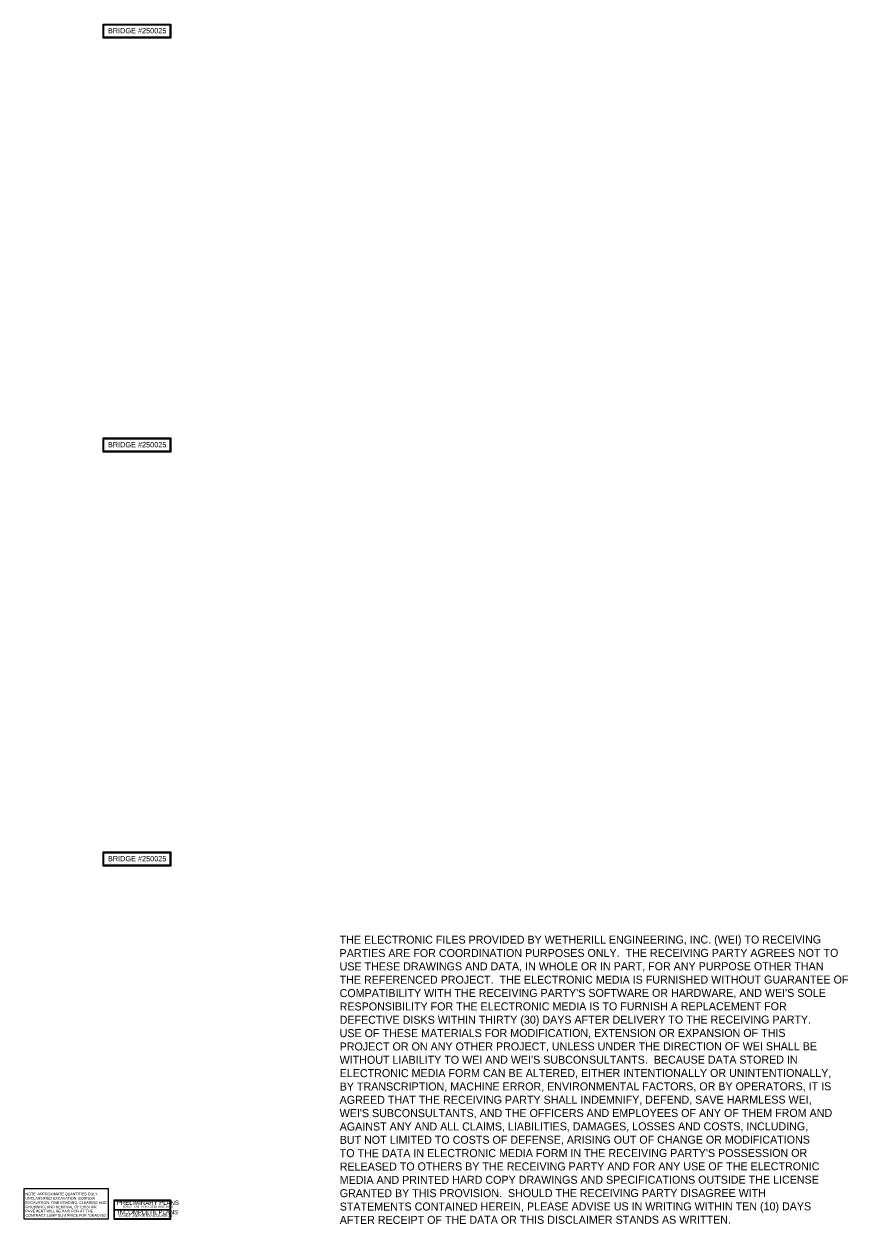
# Model space of a CAD drawing. Extents: x -8 to 533, y -20 to 768.
# Drawn here: x 313.8 to 532.8, y 1.2 to 320 of the extents above; entities that cross this region are included whole.
import ezdxf

# ---------------------------------------------------------------- set-up
doc = ezdxf.new("R2010")
doc.units = 0
for name, color, linetype in [('Default', 7, 'Continuous'), ('Old_Level_1', 7, 'Continuous'), ('Old_Level_34', 7, 'Continuous'), ('Prop Dimension', 7, 'Continuous'), ('Prop Grid Mask', 7, 'Continuous'), ('Sheet Sticker Incomplete CELL', 7, 'Continuous'), ('Sheet Sticker Preliminary CELL', 7, 'Continuous')]:
    doc.layers.add(name, color=color, linetype=linetype)

msp = doc.modelspace()

# ---------------------------------------------------------------- linework, layer by layer
at = {"layer": 'Old_Level_34'}
for points in [[(335.02, 319.75), (352.49, 319.75), (352.49, 316.46), (335.02, 316.46)], [(335.02, 209.75), (352.49, 209.75), (352.49, 206.46), (335.02, 206.46)], [(335.02, 99.75), (352.49, 99.75), (352.49, 96.46), (335.02, 96.46)]]:
    msp.add_lwpolyline(points, close=True, dxfattribs=at)
at = {"layer": 'Prop Grid Mask'}
for points in [[(334.83, 320), (352.75, 320), (352.75, 316.24), (334.83, 316.24)], [(334.83, 210), (352.75, 210), (352.75, 206.24), (334.83, 206.24)], [(334.83, 100), (352.75, 100), (352.75, 96.24), (334.83, 96.24)], [(313.75, 2.5), (336.25, 2.5), (336.25, 10.5), (313.75, 10.5)], [(352.75, 7.5), (337.6, 7.5), (337.6, 2.42), (352.75, 2.42)]]:
    msp.add_lwpolyline(points, close=True, dxfattribs=at)
at = {"layer": 'Sheet Sticker Incomplete CELL'}
msp.add_lwpolyline([(337.83, 2.57), (337.83, 4.92), (352.53, 4.92), (352.53, 2.57)], close=True, dxfattribs=at)
at = {"layer": 'Sheet Sticker Preliminary CELL'}
msp.add_lwpolyline([(337.83, 4.92), (337.83, 7.27), (352.53, 7.27), (352.53, 4.92)], close=True, dxfattribs=at)

# ---------------------------------------------------------------- texts
at = {"layer": 'Default'}
for s, p in [('THE ELECTRONIC FILES PROVIDED BY WETHERILL ENGINEERING, INC. (WEI) TO RECEIVING ', (397.66, 75.62)), ('PARTIES ARE FOR COORDINATION PURPOSES ONLY.  THE RECEIVING PARTY AGREES NOT TO ', (397.66, 72.07)), ('USE THESE DRAWINGS AND DATA, IN WHOLE OR IN PART, FOR ANY PURPOSE OTHER THAN ', (397.66, 68.53)), ('THE REFERENCED PROJECT.  THE ELECTRONIC MEDIA IS FURNISHED WITHOUT GUARANTEE OF ', (397.66, 64.98)), ("COMPATIBILITY WITH THE RECEIVING PARTY'S SOFTWARE OR HARDWARE, AND WEI'S SOLE ", (397.67, 61.44)), ('RESPONSIBILITY FOR THE ELECTRONIC MEDIA IS TO FURNISH A REPLACEMENT FOR ', (397.67, 57.89)), ('DEFECTIVE DISKS WITHIN THIRTY (30) DAYS AFTER DELIVERY TO THE RECEIVING PARTY.  ', (397.67, 54.35)), ('USE OF THESE MATERIALS FOR MODIFICATION, EXTENSION OR EXPANSION OF THIS ', (397.67, 50.8)), ('PROJECT OR ON ANY OTHER PROJECT, UNLESS UNDER THE DIRECTION OF WEI SHALL BE ', (397.67, 47.26)), ("WITHOUT LIABILITY TO WEI AND WEI'S SUBCONSULTANTS.  BECAUSE DATA STORED IN ", (397.67, 43.71)), ('ELECTRONIC MEDIA FORM CAN BE ALTERED, EITHER INTENTIONALLY OR UNINTENTIONALLY, ', (397.68, 40.17)), ('BY TRANSCRIPTION, MACHINE ERROR, ENVIRONMENTAL FACTORS, OR BY OPERATORS, IT IS ', (397.68, 36.62)), ('AGREED THAT THE RECEIVING PARTY SHALL INDEMNIFY, DEFEND, SAVE HARMLESS WEI, ', (397.68, 33.08)), ("WEI'S SUBCONSULTANTS, AND THE OFFICERS AND EMPLOYEES OF ANY OF THEM FROM AND ", (397.68, 29.54)), ('AGAINST ANY AND ALL CLAIMS, LIABILITIES, DAMAGES, LOSSES AND COSTS, INCLUDING, ', (397.68, 25.99)), ('BUT NOT LIMITED TO COSTS OF DEFENSE, ARISING OUT OF CHANGE OR MODIFICATIONS ', (397.69, 22.45)), ("TO THE DATA IN ELECTRONIC MEDIA FORM IN THE RECEIVING PARTY'S POSSESSION OR ", (397.69, 18.9)), ('RELEASED TO OTHERS BY THE RECEIVING PARTY AND FOR ANY USE OF THE ELECTRONIC ', (397.69, 15.36)), ('MEDIA AND PRINTED HARD COPY DRAWINGS AND SPECIFICATIONS OUTSIDE THE LICENSE ', (397.69, 11.81)), ('GRANTED BY THIS PROVISION.  SHOULD THE RECEIVING PARTY DISAGREE WITH ', (397.69, 8.27)), ('STATEMENTS CONTAINED HEREIN, PLEASE ADVISE US IN WRITING WITHIN TEN (10) DAYS ', (397.69, 4.72)), ('AFTER RECEIPT OF THE DATA OR THIS DISCLAIMER STANDS AS WRITTEN.', (397.7, 1.18))]:
    msp.add_text(s, height=2.127, rotation=0.0298, dxfattribs=at).set_placement(p)
at = {"layer": 'Old_Level_1'}
for p in [(336.07, 317.52), (336.07, 207.52), (336.07, 97.52)]:
    msp.add_text('BRIDGE #250025', height=1.4062, rotation=360, dxfattribs=at).set_placement(p)
at = {"layer": 'Prop Dimension'}
for s, p in [('NOTE: APPROXIMATE QUANTITIES ONLY. ', (314.16, 8.78)), ('UNCLASSIFIED EXCAVATION, BORROW ', (314.16, 7.64)), ('EXCAVATION, FINE GRADING, CLEARING AND ', (314.16, 6.5)), ('GRUBBING, AND REMOVAL OF EXISTING ', (314.16, 5.36)), ('CONTRACT LUMP SUM PRICE FOR "GRADING."', (314.16, 3.09)), ('PAVEMENT WILL BE PAID FOR AT THE ', (314.16, 4.22))]:
    msp.add_text(s, height=0.7, dxfattribs=at).set_placement(p)
at = {"layer": 'Sheet Sticker Incomplete CELL'}
for s, height, p in [('INCOMPLETE PLANS', 1.152, (338.72, 3.74)), ('DO NOT USE FOR R/W ACQUISITION', 0.576, (339.05, 3.05))]:
    msp.add_text(s, height=height, dxfattribs=at).set_placement(p)
at = {"layer": 'Sheet Sticker Preliminary CELL'}
for s, height, p in [('PRELIMINARY PLANS', 1.152, (338.48, 6.24)), ('DO NOT USE FOR CONSTRUCTION', 0.576, (339.79, 5.47))]:
    msp.add_text(s, height=height, dxfattribs=at).set_placement(p)

doc.saveas('drawing.dxf')
